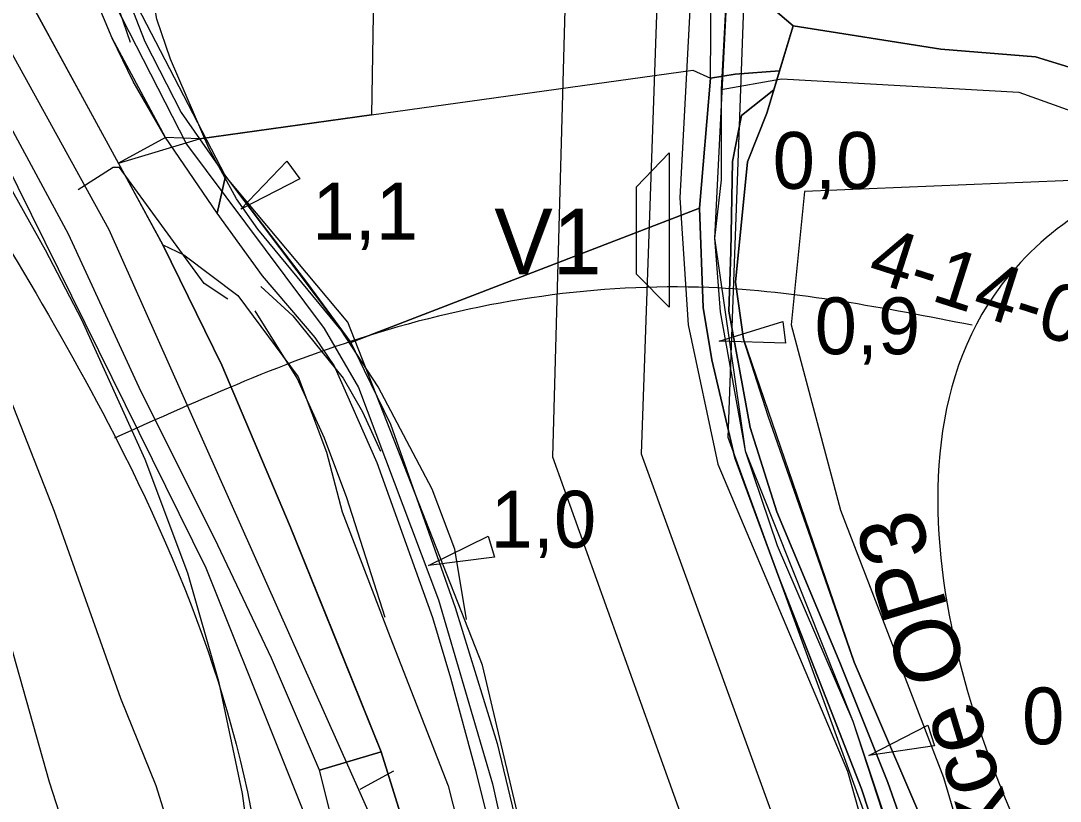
# Model space of a CAD drawing. Extents: x -684583 to -680383, y -1157874 to -1154904.
# Drawn here: x -683125.8 to -682887.9, y -1157503 to -1157324.4 of the extents above; entities that cross this region are included whole.
import ezdxf

# ---------------------------------------------------------------- set-up
doc = ezdxf.new("R2010")
doc.units = 0
for name, color, linetype in [('01_DOPRAVA', 7, 'Continuous'), ('01_OBVOD PÚ', 7, 'Continuous'), ('01_PRVKY PRŮZKUMU', 7, 'Continuous'), ('01_PRVKY PSZ', 7, 'Continuous'), ('01_SPRÁV_HRANICE', 7, 'Continuous'), ('01_VRSTEVNICE', 7, 'Continuous'), ('02_KULTURY STAV', 7, 'Continuous'), ('03_PC_OBJEKTY_NÁVRH', 7, 'Continuous'), ('03_PC_STAV', 7, 'Continuous'), ('04_ZPF_OP_ORGAN', 7, 'Continuous'), ('05_VHO_V_TOK', 7, 'Continuous'), ('06_BIOGEOGRAFIE', 7, 'Continuous'), ('06_ÚSES_BC', 7, 'Continuous'), ('06_ÚSES_BK', 7, 'Continuous'), ('07_OCH_P A POPISY TI', 7, 'Continuous'), ('07_PLYNOVOD', 7, 'Continuous')]:
    doc.layers.add(name, color=color, linetype=linetype)

msp = doc.modelspace()

# ---------------------------------------------------------------- linework, layer by layer
at = {"layer": '01_DOPRAVA'}
msp.add_lwpolyline([(-683054.51, -1157758.92), (-683045.66, -1157702.14), (-683033.32, -1157625.99), (-683033.32, -1157571.3), (-683045.07, -1157508.09), (-683105.62, -1157372.25), (-683148.82, -1157294.04), (-683163.81, -1157254.05), (-683168.81, -1157196.71), (-683165.28, -1157159.67), (-683135.89, -1157075.28), (-683079.46, -1156981.49), (-683035.96, -1156902.98), (-682993.94, -1156817.72), (-682972.78, -1156716.87), (-682952.5, -1156631.31), (-682921.05, -1156497.23), (-682883.43, -1156372.57), (-682870.79, -1156344.34), (-682802.61, -1156200.56), (-682782.62, -1156147.93)], dxfattribs=at)
at = {"layer": '01_OBVOD PÚ'}
msp.add_lwpolyline([(-682865.53, -1157341.29), (-682893.56, -1157332.68), (-682915.26, -1157330.93), (-682949.07, -1157325.62), (-682955.11, -1157345.57), (-682959.54, -1157356.74), (-682962.28, -1157384.25), (-682960.41, -1157397.25), (-682935.1, -1157471.19), (-682915.62, -1157516.47), (-682909.09, -1157538.97), (-682901.39, -1157578.47), (-682901.33, -1157603.49), (-682912.12, -1157648.58), (-682925.59, -1157713.72), (-682932.97, -1157763.18), (-682930, -1157800.25), (-682921.17, -1157813.46), (-682989.26, -1157839.49)], dxfattribs=at)
at = {"layer": '01_PRVKY PRŮZKUMU'}
for points in [[(-683025.92, -1157705.32), (-683022.15, -1157651.71), (-683000.24, -1157609.57), (-682997.99, -1157594.15), (-682997.99, -1157565.8), (-683020.17, -1157471.89), (-683050.97, -1157393.39), (-683079.01, -1157360), (-683101.29, -1157316.95)], [(-682879.89, -1157360.72), (-682946.46, -1157363.51), (-682949.54, -1157394.01), (-682938.25, -1157436.4), (-682914.65, -1157497.57), (-682890.98, -1157577.72), (-682890.98, -1157606.89), (-682909.88, -1157693.41)]]:
    msp.add_lwpolyline(points, dxfattribs=at)
at = {"layer": '01_PRVKY PSZ'}
msp.add_lwpolyline([(-682951.59, -1157030.23), (-682949.58, -1157052.3), (-682959.2, -1157265.52), (-682962.61, -1157285.78), (-682967.05, -1157374.21), (-682960.06, -1157422.81), (-682935.41, -1157484.7), (-682916.27, -1157543.42), (-682905.44, -1157579.25), (-682923.84, -1157669.47), (-682932.49, -1157713.29), (-682940.15, -1157759.63), (-682931.41, -1157813.92)], dxfattribs=at)
at = {"layer": '01_SPRÁV_HRANICE'}
msp.add_lwpolyline([(-682865.53, -1157341.29), (-682893.56, -1157332.68), (-682915.26, -1157330.93), (-682949.07, -1157325.62), (-682955.11, -1157345.57), (-682959.54, -1157356.74), (-682962.28, -1157384.25), (-682960.41, -1157397.25), (-682935.1, -1157471.19), (-682915.62, -1157516.47), (-682909.09, -1157538.97), (-682901.39, -1157578.47), (-682901.33, -1157603.49), (-682912.12, -1157648.58), (-682925.59, -1157713.72), (-682932.97, -1157763.18), (-682930, -1157800.25), (-682921.17, -1157813.46), (-682989.26, -1157839.49)], dxfattribs=at)
at = {"layer": '01_VRSTEVNICE'}
for points in [[(-683023.82, -1157461.43), (-683026.53, -1157445.31), (-683031.66, -1157431.62), (-683044.07, -1157408.22), (-683052.49, -1157395.24), (-683071.6, -1157372.13), (-683076.45, -1157365.14), (-683082.73, -1157353.73), (-683091.57, -1157333.19), (-683094.71, -1157324.06), (-683098.99, -1157298.96), (-683101.27, -1157293.97), (-683110.4, -1157279.84), (-683115.68, -1157266.15), (-683117.96, -1157247.89), (-683117.96, -1157238.76), (-683116.82, -1157227.35), (-683113.54, -1157213.66), (-683113.54, -1157209.09), (-683117.25, -1157199.96), (-683118.1, -1157192.4), (-683117.39, -1157189.98), (-683109.4, -1157182.28), (-683093.14, -1157173)], [(-683115.11, -1157279.99), (-683109.54, -1157297.25), (-683105.55, -1157315.5), (-683100.84, -1157329.34)], [(-683136.36, -1157347.17), (-683133.65, -1157353.16), (-683120.24, -1157376.84), (-683111.97, -1157392.82), (-683097.42, -1157424.77), (-683087.72, -1157450.73), (-683080.59, -1157475.55), (-683075.17, -1157501.23), (-683070.74, -1157533.75), (-683069.03, -1157555.43), (-683069.46, -1157575.4), (-683071.74, -1157590.38)], [(-683078.45, -1157388.11), (-683083.87, -1157384.54), (-683103.27, -1157358.01), (-683104.69, -1157358.01), (-683112.68, -1157363.15)], [(-683070.89, -1157385.26), (-683063.61, -1157391.96), (-683052.06, -1157406.23), (-683047.64, -1157413.93), (-683043.5, -1157422.91)], [(-683042.46, -1157461), (-683051.2, -1157433.61), (-683056.34, -1157419.92), (-683062.61, -1157406.23), (-683072.17, -1157390.82)], [(-683127.66, -1157640.16), (-683107.12, -1157627.61), (-683101.13, -1157622.33), (-683094.85, -1157613.63), (-683088.43, -1157599.37), (-683084.44, -1157585.1), (-683083.3, -1157565.13), (-683086.15, -1157545.16), (-683088.15, -1157525.19), (-683091.29, -1157510.93), (-683094.85, -1157499.52), (-683102.98, -1157479.54), (-683118.1, -1157436.75), (-683128.94, -1157409.08)], [(-683127.8, -1157625.61), (-683117.1, -1157616.63), (-683111.83, -1157609.92), (-683107.41, -1157602.36), (-683104.12, -1157593.66), (-683102.13, -1157585.1), (-683100.99, -1157576.54), (-683100.84, -1157562.85), (-683102.27, -1157554.29), (-683106.83, -1157537.17), (-683119.24, -1157498.66), (-683131.37, -1157455.87)], [(-683040.52, -1157496.14), (-683048.21, -1157500.37)]]:
    msp.add_lwpolyline(points, dxfattribs=at)
at = {"layer": '02_KULTURY STAV'}
for points in [[(-683092.93, -1157130.42), (-683106.43, -1157165.69), (-683118.57, -1157201.97), (-683120.22, -1157223.29), (-683120.73, -1157236.27), (-683120.05, -1157251.32), (-683117.34, -1157269.31), (-683109.5, -1157295.71), (-683104.67, -1157310.58), (-683097.47, -1157329.16), (-683089.13, -1157345.4), (-683079.01, -1157360), (-683060.22, -1157384.58), (-683050.32, -1157398.08), (-682970.5, -1157367.3), (-682967.98, -1157337.6), (-682967.71, -1157306.5), (-682965.68, -1157276.1), (-682963.63, -1157251.67), (-682961.95, -1157195.51), (-682958.06, -1157123.89)], [(-683057.49, -1157495.91), (-683068.49, -1157470.25), (-683080.77, -1157444.4), (-683098.71, -1157408.35), (-683114.94, -1157373.25), (-683141.41, -1157324.29), (-683156.77, -1157295.63), (-683162.73, -1157282.87), (-683167.85, -1157267.78), (-683167.85, -1157267.78), (-683174.7, -1157241.69), (-683177.2, -1157220.47), (-683177.86, -1157201.14), (-683157.35, -1157217.4), (-683155.26, -1157236.73), (-683150.78, -1157255.94), (-683140.8, -1157285.4), (-683131.12, -1157306.73), (-683123.39, -1157320.54), (-683093.3, -1157375.73), (-683079.83, -1157403.21), (-683064.17, -1157440.15), (-683054.58, -1157463.9), (-683043.34, -1157491.71)], [(-682959.34, -1157293.71), (-682952.5, -1157293.15), (-682878.23, -1157311.8), (-682748.43, -1157354.76), (-682714.66, -1157361.21), (-682714.81, -1157364.46), (-682721.9, -1157375.47), (-682727.54, -1157391.58), (-682729.36, -1157393.83), (-682766.68, -1157385.47), (-682797.96, -1157374.23), (-682829.22, -1157360.16), (-682865.53, -1157341.29), (-682893.56, -1157332.68), (-682915.26, -1157330.93), (-682949.07, -1157325.62), (-682960.72, -1157315.58)], [(-683050.32, -1157398.08), (-683047.27, -1157404.35), (-683041.25, -1157416.74), (-683026.4, -1157458.67), (-683016.79, -1157489.83), (-683009.51, -1157520.25), (-683007.03, -1157531.61), (-683002.19, -1157556.27), (-683000.27, -1157567.73), (-682999.3, -1157594.75), (-683001.56, -1157607.79), (-682917.01, -1157621.2), (-682912.42, -1157603.36), (-682910.6, -1157586.57), (-682913.64, -1157569.71), (-682917.54, -1157549.63), (-682923.67, -1157529.91), (-682933.41, -1157500.16), (-682952.33, -1157451.75), (-682962.44, -1157424.45), (-682967.7, -1157402.05), (-682969.62, -1157390.02), (-682970.5, -1157367.3)], [(-683093.3, -1157375.73), (-683088.54, -1157377.96), (-683076.17, -1157387.28), (-683062.38, -1157405.88), (-683055.9, -1157423.11), (-683052.29, -1157436.79), (-683041.28, -1157465.46), (-683028.05, -1157499.48), (-683015.51, -1157548.59), (-683011.68, -1157572.3), (-683011.64, -1157580.2), (-683015.05, -1157594.84), (-683018, -1157604.18), (-683022.23, -1157611), (-683025.32, -1157614.52), (-683025.15, -1157605.08), (-683025.21, -1157590.49), (-683026.1, -1157570.61), (-683028.44, -1157548.59), (-683034.27, -1157520.87), (-683043.34, -1157491.71), (-683064.17, -1157440.15), (-683079.83, -1157403.21)]]:
    msp.add_lwpolyline(points, close=True, dxfattribs=at)
for points in [[(-682960.72, -1157315.58), (-682949.07, -1157325.62), (-682952.17, -1157335.86), (-682962.32, -1157336.66), (-682967.98, -1157337.6), (-682967.71, -1157306.5)], [(-683104.67, -1157310.58), (-683097.47, -1157329.16), (-683089.13, -1157345.4), (-683084.94, -1157351.45), (-683079.01, -1157360), (-683080.89, -1157368.49), (-683092.7, -1157351.15), (-683104.91, -1157328.42), (-683109.86, -1157316.49)], [(-683033.42, -1157692.12), (-683034.08, -1157686.53), (-683031.58, -1157681.33), (-683027.44, -1157644.4), (-683025.58, -1157637.78), (-683013.37, -1157615.15), (-683007.58, -1157605.24), (-683007.18, -1157597.21), (-683007.87, -1157584.65), (-683006.31, -1157572.11), (-683007.34, -1157559.25), (-683013.9, -1157527.23), (-683021.51, -1157496.5), (-683027.43, -1157474.84), (-683031.55, -1157461.02), (-683044.3, -1157425.6), (-683054.13, -1157403.28), (-683058.47, -1157396.94), (-683070.54, -1157382.77), (-683080.89, -1157368.49), (-683092.7, -1157351.15), (-683100.09, -1157338.35), (-683104.91, -1157328.42), (-683109.86, -1157316.49)], [(-683123.39, -1157320.54), (-683093.3, -1157375.73), (-683088.54, -1157377.96), (-683076.17, -1157387.28), (-683062.38, -1157405.88), (-683055.9, -1157423.11), (-683052.29, -1157436.79), (-683041.28, -1157465.46), (-683028.05, -1157499.48), (-683015.51, -1157548.59), (-683011.68, -1157572.3), (-683011.64, -1157580.2), (-683015.05, -1157594.84), (-683018, -1157604.18), (-683025.32, -1157614.52), (-683034.2, -1157674.95), (-683041.64, -1157716.25)], [(-682919.76, -1157520.36), (-682927.4, -1157498.74), (-682938.36, -1157471.29), (-682952.76, -1157436.76), (-682958.9, -1157417.47), (-682963.8, -1157390.86), (-682963.35, -1157377.28), (-682962.93, -1157356.61), (-682960.88, -1157346.09), (-682953.49, -1157340.22), (-682952.17, -1157335.86), (-682962.32, -1157336.66), (-682967.98, -1157337.6), (-682970.5, -1157367.3), (-682969.62, -1157390.02), (-682967.7, -1157402.05), (-682962.44, -1157424.45), (-682952.33, -1157451.75), (-682933.41, -1157500.16), (-682923.67, -1157529.91)], [(-682915.62, -1157516.47), (-682935.1, -1157471.19), (-682954.75, -1157414.88), (-682960.41, -1157397.25), (-682962.28, -1157384.25), (-682959.54, -1157356.74), (-682955.11, -1157345.57), (-682953.49, -1157340.22), (-682960.88, -1157346.09), (-682962.93, -1157356.61), (-682963.35, -1157377.28), (-682963.8, -1157390.86), (-682958.9, -1157417.47), (-682952.76, -1157436.76), (-682938.36, -1157471.29), (-682927.4, -1157498.74), (-682919.76, -1157520.36)], [(-683013.9, -1157527.23), (-683021.51, -1157496.5), (-683027.43, -1157474.84), (-683031.55, -1157461.02), (-683044.3, -1157425.6), (-683054.13, -1157403.28), (-683058.47, -1157396.94), (-683070.54, -1157382.77), (-683080.89, -1157368.49), (-683079.01, -1157360), (-683050.32, -1157398.08), (-683047.27, -1157404.35), (-683041.25, -1157416.74), (-683026.4, -1157458.67), (-683016.79, -1157489.83), (-683009.51, -1157520.25)], [(-683052.69, -1157706.77), (-683048.74, -1157678.14), (-683048.22, -1157674.26), (-683047.26, -1157663.68), (-683040.52, -1157618.63), (-683039.8, -1157591.06), (-683042.49, -1157563.72), (-683043.54, -1157550.33), (-683047.17, -1157530.46), (-683052.37, -1157516.21), (-683057.49, -1157495.91), (-683043.34, -1157491.71), (-683034.27, -1157520.87), (-683028.44, -1157548.59), (-683026.1, -1157570.61), (-683025.21, -1157590.49), (-683025.32, -1157614.52), (-683034.2, -1157674.95), (-683041.64, -1157716.25)]]:
    msp.add_lwpolyline(points, dxfattribs=at)
at = {"layer": '03_PC_OBJEKTY_NÁVRH'}
msp.add_lwpolyline([(-682977.4, -1157389.94), (-682984.9, -1157382.44), (-682984.9, -1157362.44), (-682977.4, -1157354.68)], close=True, dxfattribs=at)
at = {"layer": '03_PC_STAV'}
msp.add_lwpolyline([(-682956.44, -1157024.49), (-682963.29, -1157054.08), (-682959.47, -1157076.95), (-682964.05, -1157160.08), (-682974.97, -1157364.97), (-682973.09, -1157394), (-682966.3, -1157425.87), (-682936.61, -1157496.14), (-682917.8, -1157562.99), (-682910.6, -1157586.57), (-682939.66, -1157707.13), (-682946.26, -1157762.29), (-682942.96, -1157791.01), (-682939.8, -1157807.76), (-682935.77, -1157818.43)], dxfattribs=at)
at = {"layer": '04_ZPF_OP_ORGAN'}
msp.add_lwpolyline([(-683343.12, -1157216.48), (-683255.77, -1157147.12), (-683212.14, -1157111.99), (-683188, -1157100.46), (-683171.81, -1157095.24), (-683160.28, -1157100.46), (-683176.2, -1157149.05), (-683182.23, -1157222.89), (-683169.61, -1157275.32), (-683083.46, -1157449.64), (-683050.81, -1157531.17), (-683043.68, -1157605.57), (-683055.75, -1157649.76), (-683061.24, -1157640.16), (-683077.15, -1157575.37), (-683110.35, -1157581.68), (-683135.87, -1157597.03), (-683152.6, -1157616.55), (-683323.54, -1157289.05), (-683339.45, -1157238.26)], close=True, dxfattribs=at)
at = {"layer": '05_VHO_V_TOK'}
for points in [[(-682951.59, -1157030.23), (-682949.58, -1157052.3), (-682955.19, -1157159.61), (-682959.2, -1157265.52), (-682962.61, -1157285.78), (-682965.51, -1157340.18)], [(-683104.4, -1157320.5), (-683087.93, -1157352.63), (-683056.41, -1157394.83), (-683048.58, -1157408.35), (-683030.22, -1157456.96), (-683017.89, -1157499.04), (-683003.2, -1157565.08), (-683004.5, -1157585.59), (-683004.5, -1157605.86), (-683021.68, -1157639.53), (-683026.07, -1157652.81), (-683029.03, -1157684.34), (-683031.64, -1157705.21), (-683039.46, -1157727.73), (-683041.71, -1157740.42), (-683039.58, -1157758.56), (-683025.24, -1157783.93), (-683011.26, -1157822.58), (-683004.38, -1157828.62), (-682987.38, -1157838.7)], [(-682965.51, -1157340.18), (-682951.74, -1157337.75)], [(-682951.74, -1157337.75), (-682897.4, -1157340.8), (-682848.23, -1157358.41), (-682765.6, -1157395.75), (-682730.62, -1157407.02)], [(-682965.51, -1157340.18), (-682965.51, -1157340.18), (-682965.51, -1157360.81), (-682967.05, -1157374.21), (-682965.75, -1157391.04), (-682960.06, -1157422.81), (-682952.71, -1157444.51), (-682935.41, -1157484.7), (-682921.19, -1157527.26), (-682913.96, -1157551.44), (-682907.56, -1157587.6), (-682910.05, -1157605.86), (-682921.19, -1157657.67), (-682931.03, -1157703.43), (-682937.07, -1157743.15), (-682940.15, -1157759.63), (-682933.52, -1157806.34), (-682930.91, -1157816.77)]]:
    msp.add_lwpolyline(points, dxfattribs=at)
for points in [[(-683064.93, -1157356.59), (-683061.94, -1157360.59), (-683075.45, -1157367.57)], [(-682951.45, -1157393.27), (-682950.78, -1157398.23), (-682965.98, -1157397.77)], [(-683018.84, -1157442.37), (-683017.42, -1157447.17), (-683032.51, -1157449.05)], [(-682918.23, -1157485.58), (-682916.68, -1157490.34), (-682931.72, -1157492.59)]]:
    msp.add_lwpolyline(points, close=True, dxfattribs=at)
at = {"layer": '06_BIOGEOGRAFIE'}
for points in [[(-683605.53, -1156693.94), (-683552.15, -1156773.17), (-683505.66, -1156862.74), (-683385.12, -1156876.52), (-683240.48, -1156867.91), (-682983.91, -1156935.09), (-682923.69, -1156998.38), (-682921.97, -1157094.84), (-682923.69, -1157198.19), (-682892.7, -1157272.26), (-682746.33, -1157329.1), (-682572.41, -1157337.72), (-682417.44, -1157289.49), (-682386.73, -1157266.62)], [(-683662.04, -1156787.77), (-683658.6, -1156877.34), (-683631.05, -1156927.29), (-683541.5, -1156975.52), (-683489.85, -1157028.92), (-683414.08, -1157027.2), (-683362.42, -1157025.48), (-683360.7, -1157063.37), (-683464.02, -1157132.27), (-683493.29, -1157163.28), (-683474.35, -1157189.11), (-683407.19, -1157171.89), (-683317.65, -1157115.05), (-683269.44, -1157104.71), (-683207.44, -1157173.61), (-683186.78, -1157259.74), (-683105.85, -1157416.48), (-683069.69, -1157530.17), (-683073.13, -1157580.12), (-683097.24, -1157628.35), (-683264.27, -1157657.63), (-683431.3, -1157647.3), (-683531.17, -1157605.96), (-683636.21, -1157542.23), (-683651.71, -1157521.56), (-683682.7, -1157519.83), (-683708.53, -1157528.45), (-683818.74, -1157547.39), (-683870.4, -1157518.11), (-683980.6, -1157521.56), (-684052.92, -1157490.55), (-684171.74, -1157400.98), (-684213.07, -1157375.14), (-684250.95, -1157388.92), (-684249.23, -1157437.15), (-684237.17, -1157466.44), (-684170.02, -1157518.11), (-684097.7, -1157562.9), (-684011.6, -1157605.96), (-683953.05, -1157602.51), (-683891.06, -1157626.63), (-683835.96, -1157619.74), (-683789.47, -1157599.07), (-683713.7, -1157578.4), (-683625.88, -1157592.18), (-683551.84, -1157667.97), (-683445.07, -1157736.87), (-683346.92, -1157771.32), (-683179.89, -1157767.87), (-683081.74, -1157773.04), (-683016.71, -1157810.65), (-682999.16, -1157844)], [(-682391.66, -1157338.99), (-682455.37, -1157402.72), (-682453.65, -1157490.57), (-682474.31, -1157533.63), (-682517.36, -1157516.41), (-682548.36, -1157480.24), (-682624.12, -1157464.73), (-682725.72, -1157421.67), (-682779.1, -1157392.39), (-682861.75, -1157359.66), (-682903.08, -1157387.22), (-682911.69, -1157468.18), (-682873.81, -1157562.92), (-682861.75, -1157654.21), (-682892.75, -1157709.33), (-682894.47, -1157790.29), (-682823.43, -1157844.83)], [(-682908.08, -1157394.1), (-682968.34, -1157385.49), (-683044.11, -1157395.83), (-683104.38, -1157419.94)]]:
    msp.add_spline(points, degree=3, dxfattribs=at)
at = {"layer": '06_ÚSES_BC'}
msp.add_lwpolyline([(-683034.27, -1157520.87), (-683043.34, -1157491.71), (-683052.98, -1157467.86), (-683054.58, -1157463.9), (-683064.17, -1157440.15), (-683079.83, -1157403.21), (-683093.3, -1157375.73), (-683103.51, -1157357), (-683084.94, -1157351.45), (-683045.56, -1157345.97), (-682972.05, -1157335.73), (-682967.98, -1157337.6), (-682962.32, -1157336.66), (-682952.17, -1157335.86), (-682949.07, -1157325.62), (-682915.26, -1157330.93), (-682893.56, -1157332.68), (-682865.53, -1157341.29)], dxfattribs=at)
at = {"layer": '06_ÚSES_BK'}
msp.add_lwpolyline([(-683043.1, -1157199.78), (-683045.56, -1157345.97), (-683084.94, -1157351.45), (-683092.7, -1157351.15), (-683103.51, -1157357), (-683123.39, -1157320.54)], dxfattribs=at)
at = {"layer": '07_OCH_P A POPISY TI'}
for p, q in [((-683000.07, -1157274.68), (-683004.12, -1157424.22)), ((-682963.96, -1157419.76), (-682959.11, -1157286.16)), ((-682930.42, -1157512.04), (-682963.96, -1157419.76)), ((-683004.12, -1157424.22), (-682950.45, -1157573.95))]:
    msp.add_line(p, q, dxfattribs=at)
at = {"layer": '07_PLYNOVOD'}
msp.add_lwpolyline([(-682369.73, -1156748.62), (-682856.97, -1157005.33), (-682893.69, -1157072.4), (-682917.2, -1157156.56), (-682941.77, -1157266.45), (-682978.36, -1157266.27), (-682983.87, -1157423.53), (-682924.91, -1157585.64), (-682996.21, -1157612), (-683026.05, -1157750.31), (-683062.69, -1157756.02), (-683074.55, -1157765.36), (-683106.38, -1157774.6)], dxfattribs=at)

# ---------------------------------------------------------------- texts
at = {"layer": '01_PRVKY PSZ'}
msp.add_text('rekonstrukce OP3', height=15, rotation=106.8571, dxfattribs=at).set_placement((-682874.09, -1157589.03))
at = {"layer": '03_PC_OBJEKTY_NÁVRH'}
msp.add_text('V1', height=15, dxfattribs=at).set_placement((-683017.46, -1157382.44))
at = {"layer": '05_VHO_V_TOK'}
for s, p in [('0,0', (-682953.74, -1157362.88)), ('1,1', (-683059.1, -1157374.49)), ('0,9', (-682944.14, -1157400.73)), ('1,0', (-683018.3, -1157444.98)), ('0,8', (-682896.66, -1157489.99))]:
    msp.add_text(s, height=13, dxfattribs=at).set_placement(p)
msp.add_text('4-14-01-019/007', height=13, rotation=342.2334, dxfattribs=at).set_placement((-682932.53, -1157383.6))

doc.saveas('drawing.dxf')
